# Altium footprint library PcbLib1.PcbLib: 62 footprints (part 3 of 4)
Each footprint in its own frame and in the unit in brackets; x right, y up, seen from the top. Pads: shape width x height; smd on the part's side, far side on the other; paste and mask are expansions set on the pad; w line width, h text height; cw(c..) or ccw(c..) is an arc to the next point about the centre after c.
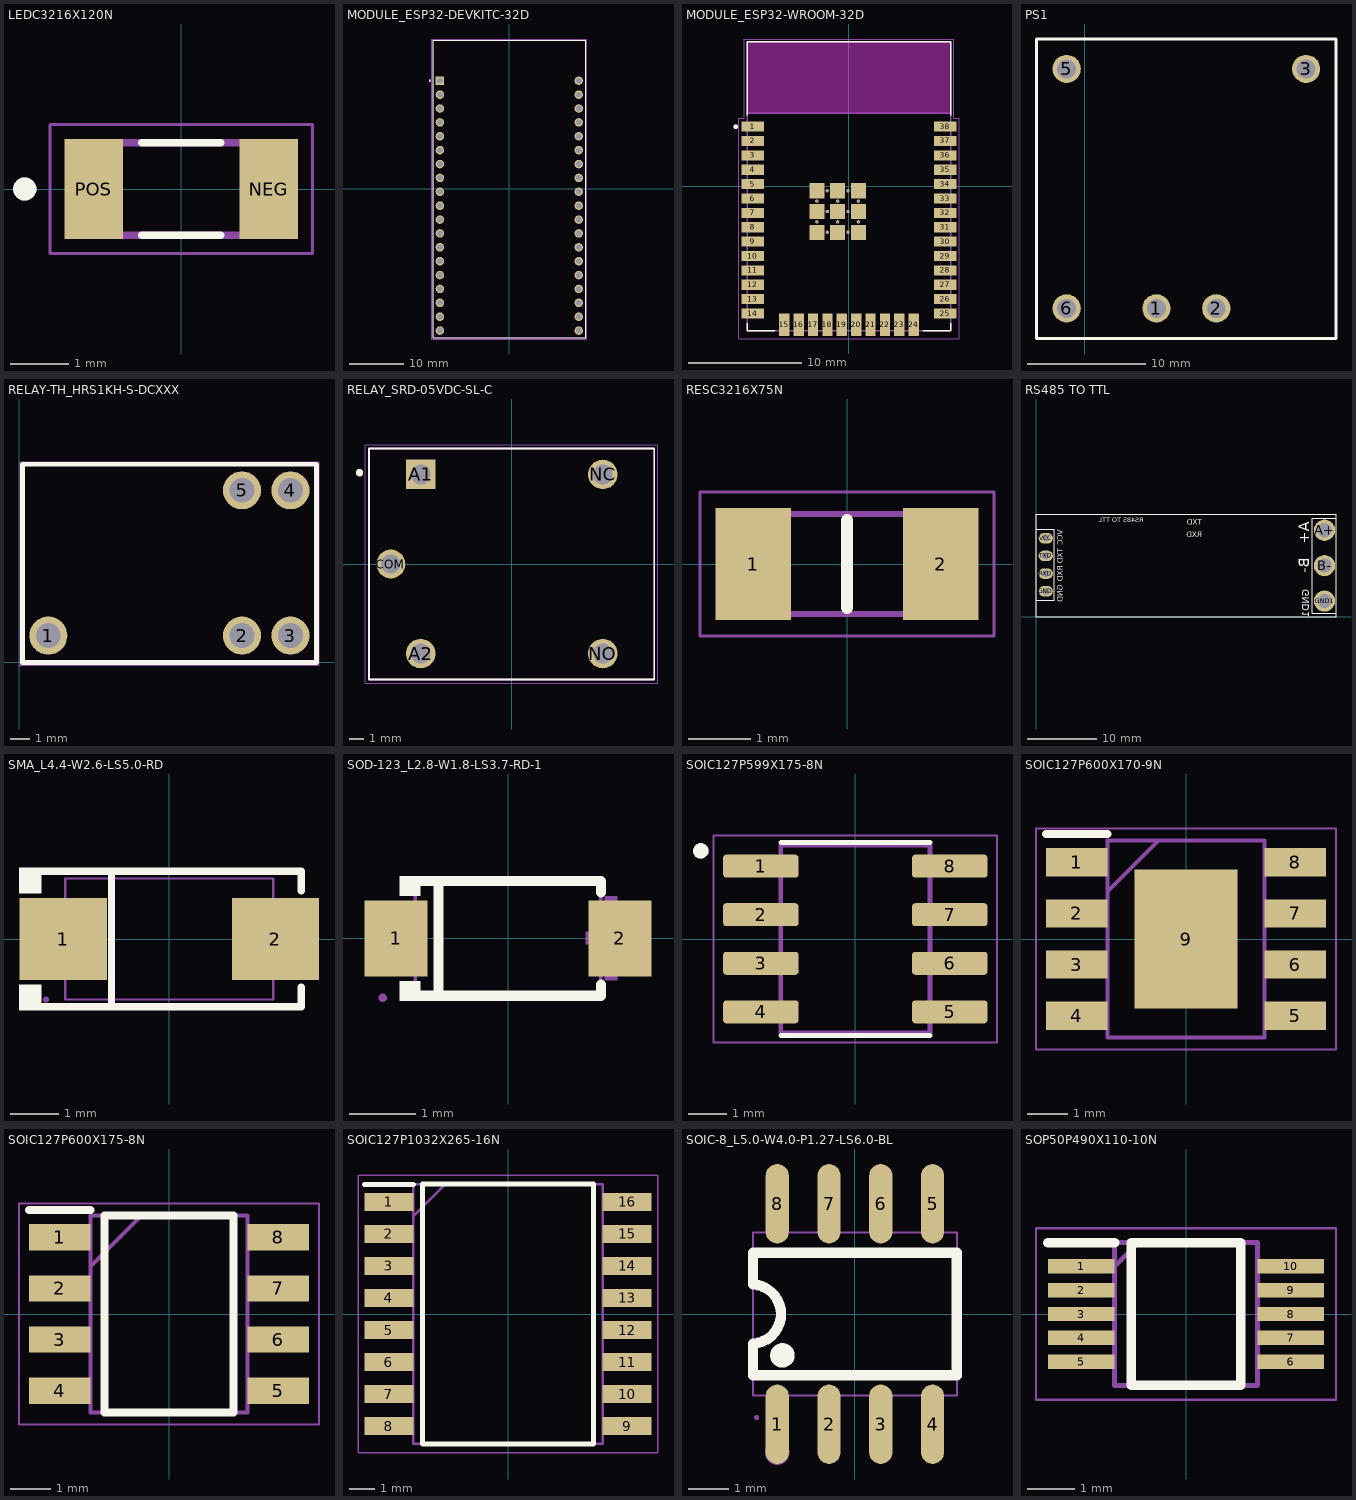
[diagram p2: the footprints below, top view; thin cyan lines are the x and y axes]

## LEDC3216X120N [mm]
height 1.2
pads (2):
  rect 1.01x1.73 smd: NEG(1.51,0) POS(-1.51,0)
Top Overlay:
  circle w0.2: c-2.7,0 r0.1
  lines w0.127: -0.685,-0.8 0.685,-0.8 ; -0.685,0.8 0.685,0.8
Mechanical 13:
  circle w0.2: c-2.7,0 r0.1
  lines w0.127: -1.6,-0.8 1.6,-0.8 1.6,0.8 -1.6,0.8 -1.6,-0.8
Mechanical 15:
  lines w0.05: -2.265,-1.115 2.265,-1.115 2.265,1.115 -2.265,1.115 -2.265,-1.115
3D body "step_temp.STEP": height 1.2, standoff 0, extent -1.6,-0.8 1.6,0.8

## MODULE_ESP32-DEVKITC-32D [mm]
pads (38):
  rect 1.56x1.56 / inner round 1.56 / far side rect 1.56x1.56 hole 1.04: J2-1(-12.7,19.76)
  round 1.56 hole 1.04: J2-2(-12.7,17.22) J2-3(-12.7,14.68) J2-4(-12.7,12.14) J2-5(-12.7,9.6) J2-6(-12.7,7.06) J2-7(-12.7,4.52) J2-8(-12.7,1.98) J2-9(-12.7,-0.56) J2-10(-12.7,-3.1) J2-11(-12.7,-5.64) J2-12(-12.7,-8.18) J2-13(-12.7,-10.72) J2-14(-12.7,-13.26) J2-15(-12.7,-15.8) J2-16(-12.7,-18.34) J2-17(-12.7,-20.88) J2-18(-12.7,-23.42) J2-19(-12.7,-25.96) J3-1(12.7,19.76) J3-2(12.7,17.22) J3-3(12.7,14.68) J3-4(12.7,12.14) J3-5(12.7,9.6) J3-6(12.7,7.06) J3-7(12.7,4.52) J3-8(12.7,1.98) J3-9(12.7,-0.56) J3-10(12.7,-3.1) J3-11(12.7,-5.64) J3-12(12.7,-8.18) J3-13(12.7,-10.72) J3-14(12.7,-13.26) J3-15(12.7,-15.8) J3-16(12.7,-18.34) J3-17(12.7,-20.88) J3-18(12.7,-23.42) J3-19(12.7,-25.96)
Top Overlay:
  circle w0.2: c-14.6,19.76 r0.1
  lines w0.127: -13.95,-27.25 13.95,-27.25 13.95,27.15 -13.95,27.15 -13.95,-27.25
Mechanical 13:
  circle w0.2: c-14.6,19.76 r0.1
  lines w0.127: -13.95,-27.25 -13.95,27.15 13.95,27.15 13.95,-27.25 -13.95,-27.25
Mechanical 15:
  lines w0.05: -14.2,-27.5 -14.2,27.4 14.2,27.4 14.2,-27.5 -14.2,-27.5
3D body "step_temp.STEP": height 6.69, standoff -6, extent -13.97,-27.9 13.97,27.2

## MODULE_ESP32-WROOM-32D [mm]
height 3.2
pads (59):
  rect 2x0.9 smd: 1(-8.5,5.26) 2(-8.5,3.99) 3(-8.5,2.72) 4(-8.5,1.45) 5(-8.5,0.18) 6(-8.5,-1.09) 7(-8.5,-2.36) 8(-8.5,-3.63) 9(-8.5,-4.9) 10(-8.5,-6.17) 11(-8.5,-7.44) 12(-8.5,-8.71) 13(-8.5,-9.98) 14(-8.5,-11.25) 25(8.5,-11.25) 26(8.5,-9.98) 27(8.5,-8.71) 28(8.5,-7.44) 29(8.5,-6.17) 30(8.5,-4.9) 31(8.5,-3.63) 32(8.5,-2.36) 33(8.5,-1.09) 34(8.5,0.18) 35(8.5,1.45) 36(8.5,2.72) 37(8.5,3.99) 38(8.5,5.26)
  rect 0.9x2 smd: 15(-5.715,-12.25) 16(-4.445,-12.25) 17(-3.175,-12.25) 18(-1.905,-12.25) 19(-0.635,-12.25) 20(0.635,-12.25) 21(1.905,-12.25) 22(3.175,-12.25) 23(4.445,-12.25) 24(5.715,-12.25)
  rect 1.33x1.33 smd: 39_1(-2.835,-0.405) 39_2(-1,-0.405) 39_3(0.835,-0.405) 39_4(-2.835,-2.24) 39_5(-1,-2.24) 39_6(0.835,-2.24) 39_7(-2.835,-4.075) 39_8(-1,-4.075) 39_9(0.835,-4.075)
  round 0.3 hole 0.2: 39_10(-1.917,-0.405) 39_11(-0.082,-0.405) 39_12(-2.835,-1.322) 39_13(-1,-1.322) 39_14(0.835,-1.322) 39_15(-1.917,-2.24) 39_16(-0.082,-2.24) 39_17(-2.835,-3.157) 39_18(-1,-3.157) 39_19(0.835,-3.157) 39_20(-1.917,-4.075) 39_21(-0.082,-4.075)
Top Overlay:
  circle w0.2: c-10,5.25 r0.1
  lines w0.127: -9,-12.1 -9,-12.75 -6.55,-12.75 ; -9,6.25 -9,12.75 9,12.75 9,6.25 ; 6.55,-12.75 9,-12.75 9,-12.1
Keep-Out Layer:
  region: 9,6.45 -9,6.45 -9,12.75 9,12.75
Mechanical 13:
  circle w0.2: c-10,5.25 r0.1
  lines w0.127: -9,6.45 9,6.45 ; -9,6.45 -9,12.75 9,12.75 9,6.45 ; -9,6.45 -9,-12.75 9,-12.75 9,6.45
  text "ANTENNA" at -6,9 h1.78
Mechanical 15:
  lines w0.05: -9.75,-13.5 -9.75,6 -9.25,6 -9.25,13 9.25,13 9.25,6 9.75,6 9.75,-13.5 -9.75,-13.5
3D body "step_temp.STEP": height 3.25, standoff 0, extent -9,-12.75 9,12.75

## PS1 [mm]
pads (5):
  round 2.4 hole 1.6 paste-2539.97 mask+0.05: 1(6.096,10.855) 2(11.176,10.855) 3(18.796,31.175) 5(-1.524,31.175) 6(-1.524,10.855)
Top Overlay:
  lines w0.254: -4.064,8.315 -4.064,33.715 21.336,33.715 21.336,8.315 -4.064,8.315
Mechanical 15:
  region: -4.064,8.375 -4.039,8.375 -4.004,8.34 -4.004,8.29 -4.039,8.255 -4.064,8.255 -4.089,8.255 -4.124,8.29 -4.124,8.34 -4.089,8.375
  region: 6.096,11.355 6.195,11.355 6.379,11.279 6.52,11.138 6.596,10.954 6.596,10.756 6.52,10.572 6.379,10.431 6.195,10.355 6.096,10.355 5.997,10.355 5.813,10.431 5.672,10.572 5.596,10.756 5.596,10.954 5.672,11.138 5.813,11.279 5.997,11.355
  region: 11.176,11.355 11.275,11.355 11.459,11.279 11.6,11.138 11.676,10.954 11.676,10.756 11.6,10.572 11.459,10.431 11.275,10.355 11.176,10.355 11.077,10.355 10.893,10.431 10.752,10.572 10.676,10.756 10.676,10.954 10.752,11.138 10.893,11.279 11.077,11.355
  region: 18.796,31.675 18.895,31.675 19.079,31.599 19.22,31.458 19.296,31.274 19.296,31.076 19.22,30.892 19.079,30.751 18.895,30.675 18.796,30.675 18.697,30.675 18.513,30.751 18.372,30.892 18.296,31.076 18.296,31.274 18.372,31.458 18.513,31.599 18.697,31.675
  region: -1.524,31.675 -1.425,31.675 -1.241,31.599 -1.1,31.458 -1.024,31.274 -1.024,31.076 -1.1,30.892 -1.241,30.751 -1.425,30.675 -1.524,30.675 -1.623,30.675 -1.807,30.751 -1.948,30.892 -2.024,31.076 -2.024,31.274 -1.948,31.458 -1.807,31.599 -1.623,31.675
  region: -1.524,11.355 -1.425,11.355 -1.241,11.279 -1.1,11.138 -1.024,10.954 -1.024,10.756 -1.1,10.572 -1.241,10.431 -1.425,10.355 -1.524,10.355 -1.623,10.355 -1.807,10.431 -1.948,10.572 -2.024,10.756 -2.024,10.954 -1.948,11.138 -1.807,11.279 -1.623,11.355
  lines w0.051: -4.064,8.315 21.336,8.315 21.336,33.715 -4.064,33.715 -4.064,8.315

## RELAY-TH_HRS1KH-S-DCXXX [mm]
pads (5):
  round 2 hole 1.3: 1(1.524,1.397) 2(11.684,1.397) 3(14.224,1.397) 4(14.224,9.017) 5(11.684,9.017)
Top Overlay:
  lines w0.254: 0.173,-0.022 0.173,10.378 ; 0.173,10.388 15.573,10.388 ; 0.193,-0.022 15.593,-0.022 ; 15.593,-0.012 15.593,10.388
Mechanical 15:
  region: 0.106,-0.149 0.106,-0.124 0.071,-0.089 0.021,-0.089 -0.014,-0.124 -0.014,-0.149 -0.014,-0.173 0.021,-0.209 0.071,-0.209 0.106,-0.173
  region: 12.234,9.017 12.233,9.126 12.148,9.326 11.994,9.479 11.793,9.562 11.575,9.562 11.374,9.479 11.22,9.326 11.135,9.126 11.134,9.017 11.135,8.908 11.22,8.708 11.374,8.555 11.575,8.472 11.793,8.472 11.994,8.555 12.148,8.708 12.233,8.908
  region: 14.774,9.017 14.773,9.126 14.688,9.326 14.534,9.479 14.333,9.562 14.115,9.562 13.914,9.479 13.76,9.326 13.675,9.126 13.674,9.017 13.675,8.908 13.76,8.708 13.914,8.555 14.115,8.472 14.333,8.472 14.534,8.555 14.688,8.708 14.773,8.908
  region: 14.774,1.397 14.773,1.506 14.688,1.706 14.534,1.859 14.333,1.942 14.115,1.942 13.914,1.859 13.76,1.706 13.675,1.506 13.674,1.397 13.675,1.288 13.76,1.088 13.914,0.935 14.115,0.852 14.333,0.852 14.534,0.935 14.688,1.088 14.773,1.288
  region: 12.234,1.397 12.233,1.506 12.148,1.706 11.994,1.859 11.793,1.942 11.575,1.942 11.374,1.859 11.22,1.706 11.135,1.506 11.134,1.397 11.135,1.288 11.22,1.088 11.374,0.935 11.575,0.852 11.793,0.852 11.994,0.935 12.148,1.088 12.233,1.288
  region: 2.074,1.397 2.073,1.506 1.988,1.706 1.834,1.859 1.633,1.942 1.415,1.942 1.214,1.859 1.06,1.706 0.975,1.506 0.974,1.397 0.975,1.288 1.06,1.088 1.214,0.935 1.415,0.852 1.633,0.852 1.834,0.935 1.988,1.088 2.073,1.288
  lines w0.051: 0.046,-0.149 0.046,10.515 15.72,10.515 15.72,-0.149 0.046,-0.149
3D body "Relay_HRS1KH_S.step": height 11.81, standoff -3.1, extent 0.378,-0.043 15.878,10.457

## RELAY_SRD-05VDC-SL-C [mm]
pads (5):
  rect 1.98x1.98 / inner round 1.98 / far side rect 1.98x1.98 hole 1.32: A1(-6.1,6)
  round 1.98 hole 1.32: A2(-6.1,-6) NC(6.1,6) NO(6.1,-6)
  round 1.935 hole 1.29: COM(-8.1,0)
Top Overlay:
  circle w0.3: c-10.2,6.119 r0.1
  lines w0.127: -9.55,-7.75 9.55,-7.75 9.55,7.75 -9.55,7.75 -9.55,-7.75
Mechanical 13:
  lines w0.127: -9.55,-7.75 9.55,-7.75 9.55,7.75 -9.55,7.75 -9.55,-7.75
Mechanical 15:
  lines w0.05: -9.8,-8 9.8,-8 9.8,8 -9.8,8 -9.8,-8
3D body "step_temp.STEP": height 15.8, standoff -3, extent -9.6,-7.8 9.6,7.8

## RESC3216X75N [mm]
pads (2):
  rect 1.2x1.8 smd: 1(-1.5,0) 2(1.5,0)
Top Overlay:
  lines w0.2: 0,-0.7 0,0.7
Mechanical 13:
  lines w0.1: -1.6,-0.8 -1.6,0.8 1.6,0.8 1.6,-0.8 -1.6,-0.8
Mechanical 15:
  lines w0.05: -2.35,-1.15 -2.35,1.15 2.35,1.15 2.35,-1.15 -2.35,-1.15
3D body "CR1206-FX-1050ELF.stp": height 0.75, standoff 0, extent -1.6,-0.8 1.6,0.8

## RS485 TO TTL [mil]
pads (7):
  round 120 hole 80: A+(1630,490) B-(1630,290) GND1(1630,90)
  oval 80x60 hole 40: GND(55,145) RXD(55,245) TXD(55,345) VCC(55,445)
Top Overlay:
  region: 65,335 65,355 45,355 45,335
  region: 65,235 65,255 45,255 45,235
  region: 65,135 65,155 45,155 45,135
  region: 65,435 65,455 45,455 45,435
  lines w3.94: 0,579.92 0,0 1694.88,0 1694.88,579.94 0,579.94 ; 1.97,94.49 104.33,94.49 104.33,496.06 1.97,496.06 ; 1690.94,20 1560,20 1560,558.27 1690.94,558.27
  text "A+" at 1545.12,538.43 h60
  text "RS485 TO TTL" at 609.45,533.86 h27.56
  text "TXD" at 938.43,521.81 h31.5
  text "GND1" at 1544.72,155.75 h39.37
  text "B-" at 1543.54,334.49 h60
  text "RXD" at 938.03,451.34 h31.5
  text "GND" at 151.42,182.52 h31.5
  text "TXD" at 152.2,388.82 h31.5
  text "RXD" at 152.2,289.21 h31.5
  text "VCC" at 152.2,491.57 h31.5
3D body "RS485 TO TTL.step": height 107.89, standoff 1.52, extent -0.12,0 1694.88,580

## SMA_L4.4-W2.6-LS5.0-RD [mm]
pads (2):
  rect 1.8x1.7 smd: 1(-2.193,0) 2(2.193,0)
Top Overlay:
  region: -2.65,1.477 -2.65,0.949 -3.107,0.949 -3.107,1.477
  region: -2.65,-1.477 -2.65,-0.949 -3.107,-0.949 -3.107,-1.477
  lines w0.152: -2.726,-1.401 2.726,-1.401 2.726,-1 ; -2.726,1.401 2.726,1.401 2.726,1 ; -1.197,-1.401 -1.197,1.401
Mechanical 6:
  region: -2.451,-0.099 -2.451,0.099 -1.656,0.099 -1.656,-0.099
  region: 2.451,-0.099 2.451,0.099 1.656,0.099 1.656,-0.099
  region: 2.153,-0.663 2.153,0.663 1.954,0.663 1.954,-0.663
Mechanical 15:
  region: -2.49,-1.25 -2.49,-1.275 -2.525,-1.31 -2.575,-1.31 -2.61,-1.275 -2.61,-1.25 -2.61,-1.225 -2.575,-1.19 -2.525,-1.19 -2.49,-1.225
  region: -1.35,0.725 -1.35,-0.725 -2.55,-0.725 -2.55,0.725
  region: 1.35,-0.725 1.35,0.725 2.55,0.725 2.55,-0.725
  lines w0.051: -2.15,-1.25 -2.15,1.25 2.15,1.25 2.15,-1.25 -2.15,-1.25

## SOD-123_L2.8-W1.8-LS3.7-RD-1 [mm]
pads (2):
  rect 0.95x1.15 smd: 1(-1.692,0) 2(1.692,0)
Top Overlay:
  region: -1.33,-0.942 -1.33,-0.647 -1.635,-0.647 -1.635,-0.942
  region: -1.33,0.942 -1.33,0.647 -1.635,0.647 -1.635,0.942
  lines w0.152: -1.406,-0.866 1.406,-0.866 1.406,-0.698 ; -1.406,0.866 1.406,0.866 1.406,0.698 ; -1.049,-0.866 -1.049,0.866
Mechanical 6:
  region: 1.651,0.635 1.651,-0.629 1.461,-0.629 1.461,0.635
  region: 1.935,0.098 1.935,-0.092 1.177,-0.092 1.177,0.098
  region: -2.03,0.095 -2.03,-0.095 -1.272,-0.095 -1.272,0.095
Mechanical 15:
  region: -1.832,-0.9 -1.832,-0.925 -1.867,-0.96 -1.917,-0.96 -1.952,-0.925 -1.952,-0.9 -1.952,-0.875 -1.917,-0.84 -1.867,-0.84 -1.832,-0.875
  region: -1.892,0.35 -1.492,0.35 -1.492,-0.35 -1.892,-0.35
  region: 1.492,0.35 1.892,0.35 1.892,-0.35 1.492,-0.35
  region: 1.5,-0.35 1.38,-0.35 1.38,0.35 1.5,0.35
  region: -1.5,0.35 -1.38,0.35 -1.38,-0.35 -1.5,-0.35
  lines w0.051: -1.4,-0.9 -1.4,0.9 1.4,0.9 1.4,-0.9 -1.4,-0.9

## SOIC127P599X175-8N [mm]
pads (8):
  rrect25% 1.97x0.6 smd: 1(-2.47,1.905) 2(-2.47,0.635) 3(-2.47,-0.635) 4(-2.47,-1.905) 5(2.47,-1.905) 6(2.47,-0.635) 7(2.47,0.635) 8(2.47,1.905)
Top Overlay:
  circle w0.2: c-4.04,2.305 r0.1
  lines w0.127: -1.95,-2.525 1.95,-2.525 ; -1.95,2.525 1.95,2.525
Mechanical 13:
  circle w0.2: c-4.04,2.305 r0.1
  lines w0.127: -1.95,-2.452 1.95,-2.452 1.95,2.452 -1.95,2.452 -1.95,-2.452
Mechanical 15:
  lines w0.05: -3.705,-2.702 3.705,-2.702 3.705,2.702 -3.705,2.702 -3.705,-2.702
3D body "step_temp.STEP": height 1.75, standoff 0, extent -3,-2.45 3,2.45

## SOIC127P600X170-9N [mm]
pads (9):
  rect 1.525x0.7 smd: 1(-2.712,1.905) 2(-2.712,0.635) 3(-2.712,-0.635) 4(-2.712,-1.905) 5(2.712,-1.905) 6(2.712,-0.635) 7(2.712,0.635) 8(2.712,1.905)
  rect 2.56x3.45 smd: 9(0,0)
Top Overlay:
  lines w0.2: -3.475,2.605 -1.95,2.605
Mechanical 13:
  lines w0.1: -1.95,1.18 -0.68,2.45 ; -1.95,-2.45 1.95,-2.45 1.95,2.45 -1.95,2.45 -1.95,-2.45
Mechanical 15:
  lines w0.05: -3.725,-2.75 3.725,-2.75 3.725,2.75 -3.725,2.75 -3.725,-2.75
3D body "MP1484EN-LF-Z.stp": height 1.7, standoff 0, extent -3,-2.45 3,2.45

## SOIC127P600X175-8N [mm]
pads (8):
  rect 1.525x0.65 smd: 1(-2.712,1.905) 2(-2.712,0.635) 3(-2.712,-0.635) 4(-2.712,-1.905) 5(2.712,-1.905) 6(2.712,-0.635) 7(2.712,0.635) 8(2.712,1.905)
Top Overlay:
  lines w0.2: -3.475,2.58 -1.95,2.58 ; -1.6,-2.45 1.6,-2.45 1.6,2.45 -1.6,2.45 -1.6,-2.45
Mechanical 13:
  lines w0.1: -1.95,1.18 -0.68,2.45 ; -1.95,-2.45 1.95,-2.45 1.95,2.45 -1.95,2.45 -1.95,-2.45
Mechanical 15:
  lines w0.05: -3.725,-2.75 3.725,-2.75 3.725,2.75 -3.725,2.75 -3.725,-2.75
3D body "NE555DR.stp": height 1.75, standoff 0, extent -3,-2.45 3,2.45

## SOIC127P1032X265-16N [mm]
pads (16):
  rect 1.95x0.7 smd: 1(-4.725,4.445) 2(-4.725,3.175) 3(-4.725,1.905) 4(-4.725,0.635) 5(-4.725,-0.635) 6(-4.725,-1.905) 7(-4.725,-3.175) 8(-4.725,-4.445) 9(4.725,-4.445) 10(4.725,-3.175) 11(4.725,-1.905) 12(4.725,-0.635) 13(4.725,0.635) 14(4.725,1.905) 15(4.725,3.175) 16(4.725,4.445)
Top Overlay:
  lines w0.2: -5.7,5.145 -3.75,5.145 ; -3.4,-5.15 3.4,-5.15 3.4,5.15 -3.4,5.15 -3.4,-5.15
Mechanical 13:
  lines w0.1: -3.75,3.88 -2.48,5.15 ; -3.75,-5.15 3.75,-5.15 3.75,5.15 -3.75,5.15 -3.75,-5.15
Mechanical 15:
  lines w0.05: -5.95,-5.5 5.95,-5.5 5.95,5.5 -5.95,5.5 -5.95,-5.5
3D body "PCF8591T.stp": height 2.65, standoff 0, extent -5.162,-5.15 5.162,5.15

## SOIC-8_L5.0-W4.0-P1.27-LS6.0-BL [mil]
pads (8):
  oval 22.38x76.78 smd: 1(-75,-106.5) 2(-25,-106.5) 3(25,-106.5) 4(75,-106.5) 5(75,106.5) 6(25,106.5) 7(-25,106.5) 8(-75,106.5)
Top Overlay:
  circle w11.81: c-70,-40 r5.91
  lines w10: -98.43,-28.61 ccw(c-99.99,0) -98.23,28.59 ; -98.42,-28.61 -98.42,-59.05 98.42,-59.05 98.42,59.05 -98.42,59.05 -98.42,28.59
Mechanical 6:
  circle w11.81: c-75,-133.86 r5.91
Mechanical 15:
  region: -92.64,-100 -92.64,-100.98 -94.02,-102.36 -95.98,-102.36 -97.36,-100.98 -97.36,-100 -97.36,-99.02 -95.98,-97.64 -94.02,-97.64 -92.64,-99.02
  region: 66.93,76.38 66.93,85.63 83.07,85.63 83.07,76.38
  region: 66.93,85.24 66.93,118.11 83.07,118.11 83.07,85.24
  region: 16.93,76.38 16.93,85.63 33.07,85.63 33.07,76.38
  region: 16.93,85.24 16.93,118.11 33.07,118.11 33.07,85.24
  region: -33.07,76.38 -33.07,85.63 -16.93,85.63 -16.93,76.38
  region: -33.07,85.24 -33.07,118.11 -16.93,118.11 -16.93,85.24
  region: -83.07,76.38 -83.07,85.63 -66.93,85.63 -66.93,76.38
  region: -83.07,85.24 -83.07,118.11 -66.93,118.11 -66.93,85.24
  region: 66.93,-85.63 66.93,-76.38 83.07,-76.38 83.07,-85.63
  region: 66.93,-118.11 66.93,-85.24 83.07,-85.24 83.07,-118.11
  region: 16.93,-85.63 16.93,-76.38 33.07,-76.38 33.07,-85.63
  region: 16.93,-118.11 16.93,-85.24 33.07,-85.24 33.07,-118.11
  region: -33.07,-85.63 -33.07,-76.38 -16.93,-76.38 -16.93,-85.63
  region: -33.07,-118.11 -33.07,-85.24 -16.93,-85.24 -16.93,-118.11
  region: -83.07,-85.63 -83.07,-76.38 -66.93,-76.38 -66.93,-85.63
  region: -83.07,-118.11 -83.07,-85.24 -66.93,-85.24 -66.93,-118.11
  lines w2: -98.42,-78.74 -98.42,78.74 98.42,78.74 98.42,-78.74 -98.42,-78.74
3D body "MAX6675ISA+T.stp": height 68.9, standoff 0, extent -96.62,-116.42 96.29,119.8

## SOP50P490X110-10N [mm]
pads (10):
  rect 1.4x0.3 smd: 1(-2.2,1) 2(-2.2,0.5) 3(-2.2,0) 4(-2.2,-0.5) 5(-2.2,-1) 6(2.2,-1) 7(2.2,-0.5) 8(2.2,0) 9(2.2,0.5) 10(2.2,1)
Top Overlay:
  lines w0.2: -2.9,1.5 -1.5,1.5 ; -1.15,-1.5 1.15,-1.5 1.15,1.5 -1.15,1.5 -1.15,-1.5
Mechanical 13:
  lines w0.1: -1.5,1 -1,1.5 ; -1.5,-1.5 1.5,-1.5 1.5,1.5 -1.5,1.5 -1.5,-1.5
Mechanical 15:
  lines w0.05: -3.15,-1.8 3.15,-1.8 3.15,1.8 -3.15,1.8 -3.15,-1.8
3D body "ADS1115LIDGSR.stp": height 1.1, standoff 0, extent -2.463,-1.5 2.463,1.5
